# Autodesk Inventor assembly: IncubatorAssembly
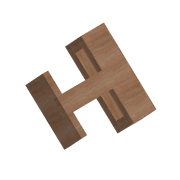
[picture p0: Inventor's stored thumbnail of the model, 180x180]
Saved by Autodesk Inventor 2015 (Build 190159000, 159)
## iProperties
Created: 2016-02
Part Number: IncubatorAssembly
Document SubType Name: Assembly
Designer: Hafliði
Author: Hafliði
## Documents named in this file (13)
- E:\Dropbox\Dropbox\Fabacademy\Bonsai incubator\IncubatorAssembly.iam
- E:\Dropbox\Dropbox\Fabacademy\Bonsai incubator\Front.ipt
- E:\Dropbox\Dropbox\Fabacademy\Bonsai incubator\Sides.ipt
- E:\Dropbox\Dropbox\Fabacademy\Bonsai incubator\Wooden support.ipt
- E:\Dropbox\Dropbox\Fabacademy\Bonsai incubator\Spine1.ipt
- E:\Dropbox\Dropbox\Fabacademy\Bonsai incubator\TopPart.ipt
- E:\Dropbox\Dropbox\Fabacademy\Bonsai incubator\Bottom.ipt
- E:\Dropbox\Dropbox\Fabacademy\Bonsai incubator\CoverFront.ipt
- E:\Dropbox\Dropbox\Fabacademy\Bonsai incubator\CoverSide.ipt
- E:\Dropbox\Dropbox\Fabacademy\Bonsai incubator\InsideFront.ipt
- E:\Dropbox\Dropbox\Fabacademy\Bonsai incubator\InsideSide.ipt
- E:\Dropbox\Dropbox\Fabacademy\Bonsai incubator\Back.ipt
- E:\Dropbox\Dropbox\Fabacademy\Bonsai incubator\CoverBack.ipt
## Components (21 placed, 12 different names)
1. Front:1 — Mate:7, Mate:8, Mate:10, Mate:11, Mate:12, Mate:13, Mate:14, Mate:27, Mate:47
2. Sides:1 — Mate:6, Mate:9, Mate:11, Mate:26, Mate:31, Mate:55, Mate:58, Mate:66
3. Sides:2 — Mate:15, Mate:16, Mate:17, Mate:24, Mate:44
4. Wooden support:1 — Mate:64, Mate:65, Mate:66, Mate:69
5. Wooden support:2 — Mate:16, Mate:17, Mate:35, Mate:42, Mate:67
6. Wooden support:3 — Mate:6, Mate:7, Mate:8, Mate:9, Mate:10, Mate:28, Mate:45
7. Wooden support:4 — Mate:12, Mate:13, Mate:14, Mate:15, Mate:24, Mate:25, Mate:39, Mate:43, Mate:46
8. Spine1:1 — Mate:52, Mate:53, Mate:54, Mate:57, Mate:58, Mate:59, Mate:60, Mate:61
9. TopPart:1 — Mate:52, Mate:53, Mate:54
10. Bottom:1 — Mate:25, Mate:26, Mate:27, Mate:30, Mate:34, Mate:38, Mate:56, Mate:57, Mate:60, Mate:62, Mate:64
11. CoverFront:2 — Mate:45, Mate:46, Mate:47
12. CoverSide:1 — Mate:43, Mate:44
13. CoverSide:2 — Mate:31
14. InsideFront:1 — Mate:38, Mate:39, Mate:40, Mate:63
15. InsideFront:2 — Mate:34, Mate:35, Mate:41, Mate:72
16. InsideSide:1 — Mate:28, Mate:30, Mate:63, Mate:72
17. InsideSide:2 — Mate:40, Mate:41, Mate:42
18. Back:1 — Mate:55, Mate:56, Mate:59, Mate:65, Mate:70
19. Back:2 — Mate:61, Mate:62, Mate:71
20. CoverBack:1 — Mate:69, Mate:70
21. CoverBack:2 — Mate:67, Mate:71
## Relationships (51: Mate 51)
- Mate:6: Sides:1 ↔ Wooden support:3
- Mate:7: Front:1 ↔ Wooden support:3
- Mate:8: Front:1 ↔ Wooden support:3
- Mate:9: Sides:1 ↔ Wooden support:3
- Mate:10: Front:1 ↔ Wooden support:3
- Mate:11: Front:1 ↔ Sides:1
- Mate:12: Front:1 ↔ Wooden support:4
- Mate:13: Front:1 ↔ Wooden support:4
- Mate:14: Front:1 ↔ Wooden support:4
- Mate:15: Sides:2 ↔ Wooden support:4
- Mate:16: Sides:2 ↔ Wooden support:2
- Mate:17: Sides:2 ↔ Wooden support:2
- Mate:24: Sides:2 ↔ Wooden support:4
- Mate:25: Wooden support:4 ↔ Bottom:1
- Mate:26: Sides:1 ↔ Bottom:1
- Mate:27: Front:1 ↔ Bottom:1
- Mate:28: Wooden support:3 ↔ InsideSide:1
- Mate:30: Bottom:1 ↔ InsideSide:1
- Mate:31: Sides:1 ↔ CoverSide:2
- Mate:34: Bottom:1 ↔ InsideFront:2
- Mate:35: Wooden support:2 ↔ InsideFront:2
- Mate:38: Bottom:1 ↔ InsideFront:1
- Mate:39: Wooden support:4 ↔ InsideFront:1
- Mate:40: InsideFront:1 ↔ InsideSide:2
- Mate:41: InsideFront:2 ↔ InsideSide:2
- Mate:42: Wooden support:2 ↔ InsideSide:2
- Mate:43: Wooden support:4 ↔ CoverSide:1
- Mate:44: Sides:2 ↔ CoverSide:1
- Mate:45: Wooden support:3 ↔ CoverFront:2
- Mate:46: Wooden support:4 ↔ CoverFront:2
- Mate:47: Front:1 ↔ CoverFront:2
- Mate:52: Spine1:1 ↔ TopPart:1
- Mate:53: Spine1:1 ↔ TopPart:1
- Mate:54: Spine1:1 ↔ TopPart:1
- Mate:55: Sides:1 ↔ Back:1
- Mate:56: Bottom:1 ↔ Back:1
- Mate:57: Spine1:1 ↔ Bottom:1
- Mate:58: Sides:1 ↔ Spine1:1
- Mate:59: Spine1:1 ↔ Back:1
- Mate:60: Spine1:1 ↔ Bottom:1
- Mate:61: Spine1:1 ↔ Back:2
- Mate:62: Bottom:1 ↔ Back:2
- Mate:63: InsideFront:1 ↔ InsideSide:1
- Mate:64: Wooden support:1 ↔ Bottom:1
- Mate:65: Wooden support:1 ↔ Back:1
- Mate:66: Sides:1 ↔ Wooden support:1
- Mate:67: Wooden support:2 ↔ CoverBack:2
- Mate:69: Wooden support:1 ↔ CoverBack:1
- Mate:70: Back:1 ↔ CoverBack:1
- Mate:71: Back:2 ↔ CoverBack:2
- Mate:72: InsideFront:2 ↔ InsideSide:1
